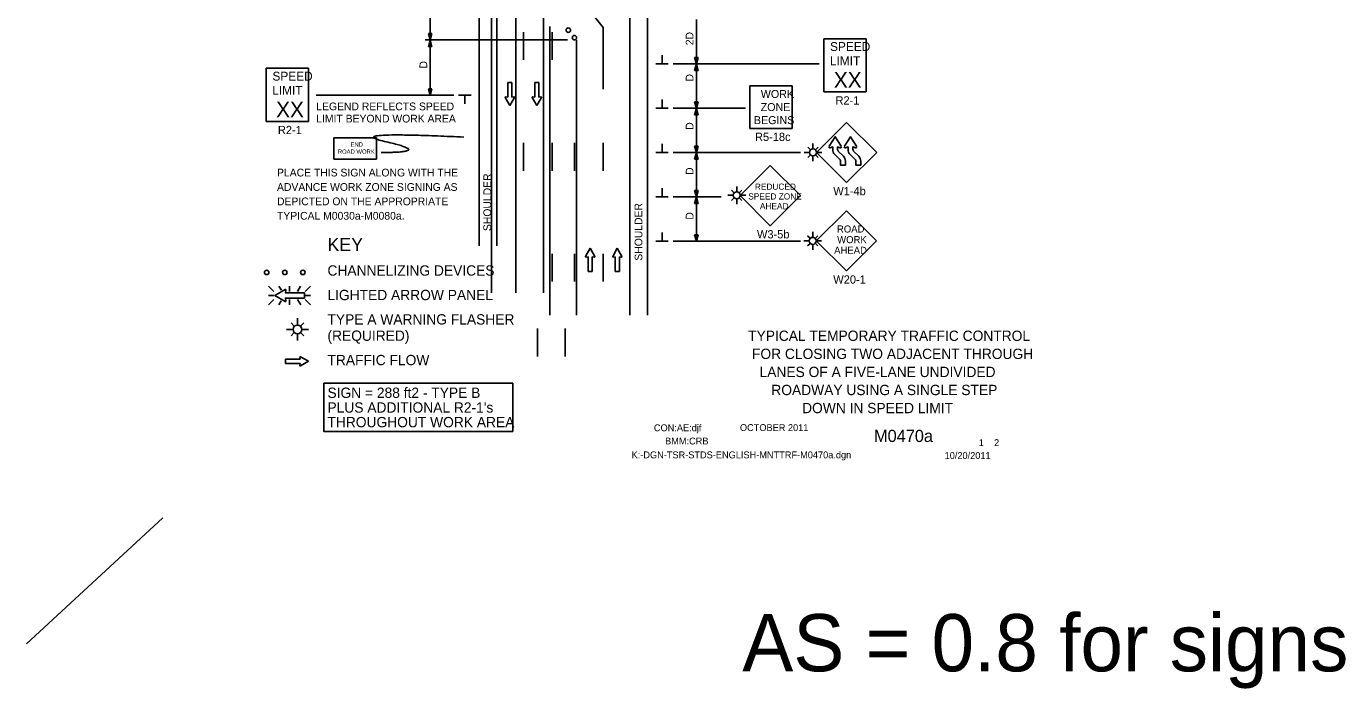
# Model space of a CAD drawing. Extents: x 16525 to 18475, y 5726 to 6926.
# Drawn here: x 16525 to 17715, y 5726 to 6323 of the extents above; entities that cross this region are included whole.
import ezdxf

# ---------------------------------------------------------------- set-up
doc = ezdxf.new("R2010")
doc.units = 0
for name, color, linetype in [('ALI_LEGAL_EX', 7, 'Continuous'), ('BORDER', 7, 'Continuous'), ('BORDER_SIGNAL_WO', 7, 'Continuous'), ('MT_SCRATCH_LEVEL_E', 7, 'Continuous'), ('PAVT_EDGE_EX', 7, 'Continuous'), ('TRAFFIC_SIGNS_PR', 7, 'Continuous'), ('TYPICAL_TEXT_DIMEN_EX', 7, 'Continuous'), ('TYPICAL_TEXT_DIMEN_PR', 7, 'Continuous')]:
    doc.layers.add(name, color=color, linetype=linetype)

msp = doc.modelspace()

# ---------------------------------------------------------------- linework, layer by layer
at = {"layer": 'ALI_LEGAL_EX'}
for points in [[(16973, 6318.2), (16973, 6293.2)], [(16999, 6318.2), (16999, 6293.2)], [(16973, 6218.2), (16973, 6193.2)], [(16999, 6218.2), (16999, 6193.2)], [(17019, 6218.2), (17019, 6193.2)], [(17045, 6218.2), (17045, 6193.2)], [(16999, 6118.2), (16999, 6093.2)], [(17019, 6118.2), (17019, 6093.2)], [(17045, 6118.2), (17045, 6093.2)]]:
    msp.add_lwpolyline(points, dxfattribs=at)
at = {"layer": 'MT_SCRATCH_LEVEL_E'}
for p, q in [((16962.7, 6272.8), (16958.9, 6272.8)), ((16958.9, 6272.8), (16958.9, 6259.6)), ((16962.7, 6272.8), (16958.9, 6272.8)), ((16958.9, 6272.8), (16958.9, 6259.6)), ((16962.7, 6259.6), (16962.7, 6272.8)), ((16962.7, 6259.6), (16962.7, 6272.8)), ((16986.9, 6272.8), (16983.2, 6272.8)), ((16983.2, 6272.8), (16983.2, 6259.6)), ((16986.9, 6272.8), (16983.2, 6272.8)), ((16983.2, 6272.8), (16983.2, 6259.6)), ((16986.9, 6259.6), (16986.9, 6272.8)), ((16986.9, 6259.6), (16986.9, 6272.8)), ((16956.7, 6259.2), (16960.8, 6252)), ((16956.7, 6259.2), (16960.8, 6252)), ((16958.9, 6259.6), (16957.1, 6259.9)), ((16958.9, 6259.6), (16957.1, 6259.9)), ((16960.8, 6252), (16964.9, 6259.2)), ((16960.8, 6252), (16964.9, 6259.2)), ((16964.4, 6259.9), (16962.7, 6259.6)), ((16964.4, 6259.9), (16962.7, 6259.6)), ((16980.9, 6259.2), (16985.1, 6252)), ((16980.9, 6259.2), (16985.1, 6252)), ((16983.2, 6259.6), (16981.4, 6259.9)), ((16983.2, 6259.6), (16981.4, 6259.9)), ((16985.1, 6252), (16989.2, 6259.2)), ((16985.1, 6252), (16989.2, 6259.2)), ((16988.7, 6259.9), (16986.9, 6259.6)), ((16988.7, 6259.9), (16986.9, 6259.6)), ((17033.2, 6123.2), (17029.1, 6115.9)), ((17033.2, 6123.2), (17029.1, 6115.9)), ((17037.4, 6115.9), (17033.2, 6123.2)), ((17037.4, 6115.9), (17033.2, 6123.2)), ((17057.7, 6123.2), (17053.6, 6115.9)), ((17057.7, 6123.2), (17053.6, 6115.9)), ((17061.9, 6115.9), (17057.7, 6123.2)), ((17061.9, 6115.9), (17057.7, 6123.2)), ((17029.6, 6115.3), (17031.4, 6115.6)), ((17029.6, 6115.3), (17031.4, 6115.6)), ((17031.4, 6115.6), (17031.4, 6102.3)), ((17031.4, 6115.6), (17031.4, 6102.3)), ((17035.1, 6102.3), (17035.1, 6115.6)), ((17035.1, 6115.6), (17036.9, 6115.3)), ((17035.1, 6102.3), (17035.1, 6115.6)), ((17035.1, 6115.6), (17036.9, 6115.3)), ((17054.1, 6115.3), (17055.9, 6115.6)), ((17054.1, 6115.3), (17055.9, 6115.6)), ((17055.9, 6115.6), (17055.9, 6102.3)), ((17055.9, 6115.6), (17055.9, 6102.3)), ((17059.6, 6102.3), (17059.6, 6115.6)), ((17059.6, 6115.6), (17061.4, 6115.3)), ((17059.6, 6102.3), (17059.6, 6115.6)), ((17059.6, 6115.6), (17061.4, 6115.3)), ((17031.4, 6102.3), (17035.1, 6102.3)), ((17031.4, 6102.3), (17035.1, 6102.3)), ((17055.9, 6102.3), (17059.6, 6102.3)), ((17055.9, 6102.3), (17059.6, 6102.3)), ((16771.7, 6023), (16758.4, 6023)), ((16758.4, 6023), (16758.4, 6019.3)), ((16771.7, 6023), (16758.4, 6023)), ((16758.4, 6023), (16758.4, 6019.3)), ((16771.3, 6024.8), (16771.7, 6023)), ((16771.3, 6024.8), (16771.7, 6023)), ((16779.3, 6021.2), (16772, 6025.3)), ((16779.3, 6021.2), (16772, 6025.3)), ((16772, 6017), (16779.3, 6021.2)), ((16772, 6017), (16779.3, 6021.2)), ((16758.4, 6019.3), (16771.7, 6019.3)), ((16758.4, 6019.3), (16771.7, 6019.3)), ((16771.7, 6019.3), (16771.3, 6017.5)), ((16771.7, 6019.3), (16771.3, 6017.5))]:
    msp.add_line(p, q, dxfattribs=at)
for centre, start, end in [((16957.1, 6259.4), 80.0362, 209.7731), ((16957.1, 6259.4), 80.0362, 209.7731), ((16964.5, 6259.4), 330.4248, 99.9638), ((16964.5, 6259.4), 330.4248, 99.9638), ((16981.3, 6259.4), 80.0362, 209.7731), ((16981.3, 6259.4), 80.0362, 209.7731), ((16988.8, 6259.4), 330.4248, 99.9638), ((16988.8, 6259.4), 330.4248, 99.9638), ((17029.5, 6115.7), 150.4248, 279.9638), ((17029.5, 6115.7), 150.4248, 279.9638), ((17037, 6115.7), 260.0362, 29.7731), ((17037, 6115.7), 260.0362, 29.7731), ((17054, 6115.7), 150.4248, 279.9638), ((17054, 6115.7), 150.4248, 279.9638), ((17061.5, 6115.7), 260.0362, 29.7731), ((17061.5, 6115.7), 260.0362, 29.7731), ((16771.8, 6024.9), 60.4248, 189.9638), ((16771.8, 6024.9), 60.4248, 189.9638), ((16771.8, 6017.4), 170.0362, 299.7731), ((16771.8, 6017.4), 170.0362, 299.7731)]:
    msp.add_arc(centre, 0.463, start, end, dxfattribs=at)
at = {"layer": 'PAVT_EDGE_EX'}
for p, q in [((16933, 6926.1), (16933, 6125.4)), ((16949, 6926.1), (16949, 6125.4)), ((17069, 6926.1), (17069, 6062.8)), ((17085, 6926.1), (17085, 6062.8)), ((16944.1, 6912.1), (16944.1, 6082.9)), ((16966.1, 6912.1), (16966.1, 6082.9)), ((16991.1, 6912.1), (16991.1, 6082.9)), ((16997, 6382), (17045, 6322.3)), ((16997, 6323.2), (16997, 6062.8)), ((17045, 6322.3), (17045, 6266.9)), ((17021, 6311.2), (17021, 6062.8))]:
    msp.add_line(p, q, dxfattribs=at)
for points in [[(16985.8, 6025.7), (16985.8, 6050.7)], [(16985.8, 6025.7), (16985.8, 6050.7)], [(17010.8, 6025.7), (17010.8, 6050.7)], [(17010.8, 6025.7), (17010.8, 6050.7)]]:
    msp.add_lwpolyline(points, dxfattribs=at)
at = {"layer": 'TRAFFIC_SIGNS_PR'}
for p, q in [((17243.9, 6312.3), (17282.3, 6312.3)), ((17243.9, 6264.3), (17243.9, 6312.3)), ((17282.3, 6264.3), (17282.3, 6312.3)), ((16740.9, 6285.6), (16779.3, 6285.6)), ((16740.9, 6237.6), (16740.9, 6285.6)), ((16779.3, 6237.6), (16779.3, 6285.6)), ((17177.1, 6231.4), (17177.1, 6269.8)), ((17177.1, 6269.8), (17215.5, 6269.8)), ((17215.5, 6231.4), (17215.5, 6269.8)), ((17243.9, 6264.3), (17282.3, 6264.3)), ((16740.9, 6237.6), (16779.3, 6237.6)), ((17237.4, 6209.7), (17264.5, 6236.8)), ((17264.5, 6236.8), (17291.7, 6209.7)), ((17177.1, 6231.4), (17215.5, 6231.4)), ((17231.7, 6212.2), (17229.6, 6214.3)), ((17234.2, 6213.2), (17234.2, 6217.7)), ((17236.7, 6212.2), (17238.8, 6214.3)), ((17261.6, 6206.2), (17256.9, 6210.9)), ((17256.9, 6210.9), (17261.6, 6206.2)), ((17275.4, 6206.2), (17270.7, 6210.9)), ((17270.7, 6210.9), (17275.4, 6206.2)), ((17231.1, 6209.7), (17226.2, 6209.7)), ((17231.7, 6207.2), (17229.6, 6205.1)), ((17234.2, 6201.7), (17234.2, 6206.1)), ((17236.7, 6207.2), (17238.8, 6205.1)), ((17237.4, 6209.7), (17242.3, 6209.7)), ((17264.5, 6182.5), (17237.4, 6209.7)), ((17258.5, 6203.2), (17253.8, 6207.9)), ((17258.5, 6203.2), (17253.8, 6207.9)), ((17259.1, 6198.1), (17259.1, 6201.8)), ((17263.5, 6198.1), (17263.5, 6201.8)), ((17291.7, 6209.7), (17264.5, 6182.5)), ((17272.3, 6203.2), (17267.6, 6207.9)), ((17272.3, 6203.2), (17267.6, 6207.9)), ((17272.9, 6198.1), (17272.9, 6201.8)), ((17277.3, 6198.1), (17277.3, 6201.8)), ((17195.7, 6197.8), (17168.6, 6170.7)), ((17222.9, 6170.7), (17195.7, 6197.8)), ((17263.5, 6198.1), (17259.1, 6198.1)), ((17277.3, 6198.1), (17272.9, 6198.1)), ((17162.9, 6173.5), (17160.8, 6175.6)), ((17165.4, 6174.5), (17165.4, 6179)), ((17168, 6173.5), (17170.1, 6175.6)), ((17162.3, 6171), (17157.5, 6171)), ((17162.9, 6168.4), (17160.8, 6166.3)), ((17165.4, 6163), (17165.4, 6167.4)), ((17168, 6168.4), (17170.1, 6166.3)), ((17168.6, 6171), (17173.5, 6171)), ((17168.6, 6170.7), (17195.7, 6143.5)), ((17195.7, 6143.5), (17222.9, 6170.7)), ((17264.3, 6157.1), (17237.1, 6129.9)), ((17291.5, 6129.9), (17264.3, 6157.1)), ((17230.8, 6129.9), (17226, 6129.9)), ((17231.5, 6132.4), (17229.3, 6134.5)), ((17234, 6133.5), (17234, 6138)), ((17236.5, 6132.4), (17238.6, 6134.5)), ((17237.1, 6129.9), (17242, 6129.9)), ((17237.1, 6129.9), (17264.3, 6102.7)), ((17264.3, 6102.7), (17291.5, 6129.9)), ((17231.5, 6127.4), (17229.3, 6125.3)), ((17234, 6121.9), (17234, 6126.3)), ((17236.5, 6127.4), (17238.6, 6125.3)), ((16743, 6089.1), (16747.9, 6084.2)), ((16747.9, 6080.6), (16743, 6080.6)), ((16754.7, 6085.3), (16752.5, 6089.1)), ((16762, 6084.2), (16762, 6089.1)), ((16769.3, 6084.2), (16772.1, 6089.1)), ((16776.2, 6084.2), (16781.1, 6089.1)), ((16776.2, 6080.6), (16781.1, 6080.6)), ((16743, 6072.1), (16747.9, 6077)), ((16752.5, 6072.1), (16754.6, 6075.8)), ((16762, 6077), (16762, 6072.1)), ((16772.2, 6072.1), (16769.3, 6077)), ((16776.2, 6077), (16781.1, 6072.1)), ((16769.2, 6054.4), (16769.2, 6060.1)), ((16769.2, 6054.4), (16769.2, 6060.1)), ((16765.3, 6050), (16759.3, 6050)), ((16765.3, 6050), (16759.3, 6050)), ((16766.1, 6053.1), (16763.5, 6055.8)), ((16766.1, 6053.1), (16763.5, 6055.8)), ((16766.1, 6046.9), (16763.5, 6044.2)), ((16766.1, 6046.9), (16763.5, 6044.2)), ((16769.2, 6040.1), (16769.2, 6045.6)), ((16769.2, 6040.1), (16769.2, 6045.6)), ((16772.4, 6053.1), (16775, 6055.8)), ((16772.4, 6053.1), (16775, 6055.8)), ((16772.4, 6046.9), (16775, 6044.2)), ((16772.4, 6046.9), (16775, 6044.2)), ((16773.2, 6050), (16779.3, 6050)), ((16773.2, 6050), (16779.3, 6050))]:
    msp.add_line(p, q, dxfattribs=at)
msp.add_lwpolyline([(16802.1, 6203.7), (16840.5, 6203.7), (16840.5, 6222.9), (16802.1, 6222.9)], close=True, dxfattribs=at)
for points in [[(17248.7, 6215.2), (17254.2, 6223.8), (17259.6, 6215.2)], [(17248.7, 6215.2), (17254.2, 6223.8), (17259.6, 6215.2)], [(17262.5, 6215.2), (17268, 6223.8), (17273.4, 6215.2)], [(17262.5, 6215.2), (17268, 6223.8), (17273.4, 6215.2)], [(17252, 6212.2), (17252, 6214.6), (17249.6, 6213.9)], [(17252, 6212.2), (17252, 6214.6), (17249.6, 6213.9)], [(17258.7, 6213.9), (17256.3, 6214.6), (17256.3, 6212.3)], [(17258.7, 6213.9), (17257.8, 6214.1), (17256.3, 6214.6), (17256.3, 6212.3)], [(17265.8, 6212.2), (17265.8, 6214.6), (17263.4, 6213.9)], [(17265.8, 6212.2), (17265.8, 6214.6), (17263.4, 6213.9)], [(17272.5, 6213.9), (17270.1, 6214.6), (17270.1, 6212.3)], [(17272.5, 6213.9), (17271.6, 6214.1), (17270.1, 6214.6), (17270.1, 6212.3)], [(17263.5, 6201.8), (17263.5, 6198.1), (17259.1, 6198.1), (17259.1, 6201.8)], [(17277.3, 6201.8), (17277.3, 6198.1), (17272.9, 6198.1), (17272.9, 6201.8)], [(16758, 6085.9), (16748.7, 6080.6), (16758, 6075.3)], [(16758.8, 6075.9), (16758.4, 6078.2), (16775.5, 6078.2), (16775.5, 6083), (16758.4, 6083), (16758.8, 6085.3)]]:
    msp.add_lwpolyline(points, dxfattribs=at)
for centre, radius in [((17013.5, 6320), 2), ((17019, 6313.2), 2), ((17234.2, 6209.7), 3.15), ((17165.4, 6171), 3.15), ((17234, 6129.9), 3.15), ((16741.5, 6101.4), 2), ((16757.8, 6101.4), 2), ((16774.1, 6101.4), 2), ((16769.2, 6050), 3.94), ((16769.2, 6050), 3.94)]:
    msp.add_circle(centre, radius, dxfattribs=at)
for centre, radius, start, end in [((17249.4, 6214.7), 0.866, 147.7292, 285.3172), ((17249.4, 6214.7), 0.866, 147.7196, 285.3201), ((17239.6, 6221), 10.8, 327.5335, 327.5431), ((17252.5, 6203.5), 10.8, 105.3192, 105.32), ((17258.2, 6212.3), 6.17, 180.6181, 225.7875), ((17258.2, 6212.3), 6.17, 180.6245, 225.2313), ((17258.2, 6212.3), 1.85, 180, 225.7875), ((17258.2, 6212.3), 1.85, 179.8762, 225.7877), ((17258.9, 6214.7), 0.864, 254.6014, 32.4796), ((17258.9, 6214.7), 0.866, 254.6148, 32.4712), ((17263.2, 6214.7), 0.866, 147.7292, 285.3172), ((17263.2, 6214.7), 0.866, 147.7196, 285.3201), ((17253.4, 6221), 10.8, 327.5335, 327.5431), ((17266.3, 6203.5), 10.8, 105.3192, 105.32), ((17272, 6212.3), 6.17, 180.6181, 225.7875), ((17272, 6212.3), 6.17, 180.6245, 225.2313), ((17272, 6212.3), 1.85, 180, 225.7875), ((17272, 6212.3), 1.85, 179.8762, 225.7877), ((17272.7, 6214.7), 0.864, 254.6014, 32.4796), ((17272.7, 6214.7), 0.866, 254.6148, 32.4712), ((17257.3, 6201.8), 1.85, 0, 47.628), ((17257.3, 6201.8), 1.85, 0, 45.7875), ((17257.3, 6201.8), 6.17, 0, 45.7875), ((17257.3, 6201.8), 6.17, 0, 45.7875), ((17257.3, 6201.8), 6.17, 0, 45.7883), ((17271.1, 6201.8), 1.85, 0, 47.628), ((17271.1, 6201.8), 1.85, 0, 45.7875), ((17271.1, 6201.8), 6.17, 0, 45.7875), ((17271.1, 6201.8), 6.17, 0, 45.7875), ((17271.1, 6201.8), 6.17, 0, 45.7883), ((16758.3, 6085.4), 0.598, 350.7308, 118.8916), ((16758.3, 6075.8), 0.597, 241.4833, 9.9593)]:
    msp.add_arc(centre, radius, start, end, dxfattribs=at)
msp.add_open_spline([(16844.7, 6209.6), (16891.9, 6209.6), (16806.9, 6228.9), (16919.2, 6223.5)], degree=2, dxfattribs=at)
at = {"layer": 'TYPICAL_TEXT_DIMEN_EX'}
msp.add_lwpolyline([(16793, 6001.4), (16963.4, 6001.4), (16963.4, 5958), (16793, 5958)], close=True, dxfattribs=at)
at = {"layer": 'TYPICAL_TEXT_DIMEN_PR'}
for p, q in [((16888.9, 6311.2), (16888.9, 6369.8)), ((17129, 6329.5), (17129, 6289.5)), ((16884.3, 6311.2), (17012.7, 6311.2)), ((16888.9, 6311.2), (16887.3, 6317)), ((16887.3, 6317), (16888.9, 6317)), ((16887.3, 6305.3), (16888.9, 6311.2)), ((16888.9, 6317), (16890.5, 6317)), ((16890.5, 6317), (16888.9, 6311.2)), ((16888.9, 6261.2), (16888.9, 6311.2)), ((16888.9, 6311.2), (16890.5, 6305.3)), ((16888.9, 6305.3), (16887.3, 6305.3)), ((16890.5, 6305.3), (16888.9, 6305.3)), ((17098.1, 6289.5), (17098.1, 6297.3)), ((17129, 6289.5), (17127.4, 6295.4)), ((17127.4, 6295.4), (17129, 6295.4)), ((17129, 6295.4), (17130.6, 6295.4)), ((17130.6, 6295.4), (17129, 6289.5)), ((17103.7, 6289.5), (17092.5, 6289.5)), ((17239.7, 6289.5), (17108, 6289.5)), ((17127.4, 6283.7), (17129, 6289.5)), ((17129, 6283.7), (17127.4, 6283.7)), ((17129, 6289.5), (17130.6, 6283.7)), ((17129, 6289.5), (17129, 6249.5)), ((17130.6, 6283.7), (17129, 6283.7)), ((16910.3, 6261.2), (16786, 6261.2)), ((16888.9, 6261.2), (16887.3, 6267)), ((16887.3, 6267), (16888.9, 6267)), ((16888.9, 6267), (16890.5, 6267)), ((16890.5, 6267), (16888.9, 6261.2)), ((16914.5, 6261.2), (16925.8, 6261.2)), ((16920.1, 6261.2), (16920.1, 6253.4)), ((17103.7, 6249.5), (17092.5, 6249.5)), ((17098.1, 6249.5), (17098.1, 6257.3)), ((17108, 6249.5), (17173.4, 6249.5)), ((17129, 6249.5), (17127.4, 6255.4)), ((17127.4, 6255.4), (17129, 6255.4)), ((17127.4, 6243.7), (17129, 6249.5)), ((17129, 6255.4), (17130.6, 6255.4)), ((17130.6, 6255.4), (17129, 6249.5)), ((17129, 6249.5), (17130.6, 6243.7)), ((17129, 6249.5), (17129, 6209.5)), ((17129, 6243.7), (17127.4, 6243.7)), ((17130.6, 6243.7), (17129, 6243.7)), ((17098.1, 6209.5), (17098.1, 6217.3)), ((17129, 6209.5), (17127.4, 6215.4)), ((17127.4, 6215.4), (17129, 6215.4)), ((17129, 6215.4), (17130.6, 6215.4)), ((17130.6, 6215.4), (17129, 6209.5)), ((17103.7, 6209.5), (17092.5, 6209.5)), ((17108, 6209.5), (17223, 6209.5)), ((17127.4, 6203.7), (17129, 6209.5)), ((17129, 6203.7), (17127.4, 6203.7)), ((17129, 6209.5), (17130.6, 6203.7)), ((17129, 6209.5), (17129, 6169.5)), ((17130.6, 6203.7), (17129, 6203.7)), ((17098.1, 6169.5), (17098.1, 6177.3)), ((17129, 6169.5), (17127.4, 6175.4)), ((17127.4, 6175.4), (17129, 6175.4)), ((17129, 6175.4), (17130.6, 6175.4)), ((17130.6, 6175.4), (17129, 6169.5)), ((17103.7, 6169.5), (17092.5, 6169.5)), ((17151.5, 6169.5), (17108, 6169.5)), ((17127.4, 6163.7), (17129, 6169.5)), ((17129, 6163.7), (17127.4, 6163.7)), ((17129, 6169.5), (17130.6, 6163.7)), ((17129, 6169.5), (17129, 6129.5)), ((17130.6, 6163.7), (17129, 6163.7)), ((17103.7, 6129.5), (17092.5, 6129.5)), ((17098.1, 6129.5), (17098.1, 6137.3)), ((17108, 6129.5), (17223, 6129.5)), ((17129, 6129.5), (17127.4, 6135.4)), ((17127.4, 6135.4), (17129, 6135.4)), ((17129, 6135.4), (17130.6, 6135.4)), ((17130.6, 6135.4), (17129, 6129.5)), ((16647.8, 5880), (16524.8, 5766.2))]:
    msp.add_line(p, q, dxfattribs=at)

# ---------------------------------------------------------------- texts
at = {"layer": 'BORDER'}
for s, p in [('TYPICAL TEMPORARY TRAFFIC CONTROL', (17175.7, 6039.6)), ('FOR CLOSING TWO ADJACENT THROUGH', (17179.2, 6023.3)), ('LANES OF A FIVE-LANE UNDIVIDED', (17186, 6007)), ('ROADWAY USING A SINGLE STEP', (17196.6, 5990.7)), ('DOWN IN SPEED LIMIT', (17224.4, 5974.4))]:
    msp.add_text(s, height=9.3, dxfattribs=at).set_placement(p)
at = {"layer": 'BORDER_SIGNAL_WO'}
for s, height, p in [('CON:AE:djf', 6.2, (17090.7, 5958.1)), ('    OCTOBER 2011    ', 6.2, (17159.1, 5958.3)), ('BMM:CRB   ', 6.2, (17100.8, 5946.2)), ('    M0470a   ', 11, (17272.9, 5948.4)), (' 1    2 ', 6.2, (17381.4, 5944.7)), ('K:-DGN-TSR-STDS-ENGLISH-MNTTRF-M0470a.dgn        ', 6.2, (17070.6, 5933.7)), ('10/20/2011    ', 6.2, (17352.9, 5933.1)), ('AS = 0.8 for signs', 51.61, (17170.4, 5741.5))]:
    msp.add_text(s, height=height, dxfattribs=at).set_placement(p)
at = {"layer": 'TRAFFIC_SIGNS_PR'}
for s, height, p in [('SPEED', 8, (17249.6, 6301.2)), ('LIMIT', 8, (17249.5, 6288.4)), ('SPEED', 8, (16746.7, 6274.5)), ('XX', 14.03, (17253, 6268.1)), ('LIMIT', 8, (16746.5, 6261.7)), ('WORK', 7.22, (17187.1, 6258.8)), ('R2-1', 7.44, (17254.5, 6252.9)), ('XX', 14.03, (16750, 6241.4)), ('ZONE', 7.22, (17187, 6247)), ('BEGINS', 7.22, (17180.9, 6235.2)), ('R2-1', 7.44, (16751.6, 6226.2)), ('R5-18c', 7.44, (17181.9, 6220)), ('ROAD WORK', 3.83, (16805.7, 6208.5)), ('END', 3.83, (16817.1, 6214.9)), ('PLACE THIS SIGN ALONG WITH THE', 7, (16750.8, 6188)), ('ADVANCE WORK ZONE SIGNING AS', 7, (16750.8, 6175)), ('REDUCED', 5.6, (17181.8, 6176)), ('W1-4b', 7.44, (17252.5, 6171.1)), ('DEPICTED ON THE APPROPRIATE', 7, (16750.8, 6162)), ('SPEED ZONE', 5.6, (17175.8, 6167.2)), ('AHEAD', 5.6, (17186.3, 6158.4)), ('TYPICAL M0030a-M0080a.', 7, (16750.8, 6149)), ('W3-5b', 7.44, (17183.7, 6132.1)), ('ROAD', 6.41, (17255.8, 6137.4)), ('WORK', 6.41, (17256, 6127.8)), ('AHEAD', 6.41, (17253.3, 6118.2)), ('W20-1', 7.45, (17252.5, 6091.3))]:
    msp.add_text(s, height=height, dxfattribs=at).set_placement(p)
at = {"layer": 'TYPICAL_TEXT_DIMEN_EX'}
for s, height, p in [('KEY', 12, (16796.3, 6120.6)), ('CHANNELIZING DEVICES', 9.3, (16796.3, 6098.5)), ('LIGHTED ARROW PANEL', 9.3, (16796.3, 6076.4)), ('TYPE A WARNING FLASHER', 9.3, (16796.3, 6054.4)), ('(REQUIRED)', 9.3, (16796.3, 6039.7)), ('TRAFFIC FLOW', 9.3, (16796.3, 6017.7)), ('SIGN = 288 ft2 - TYPE B', 9.3, (16796.3, 5988.2)), ("PLUS ADDITIONAL R2-1's", 9.3, (16796.3, 5974.9)), ('THROUGHOUT WORK AREA', 9.3, (16796.3, 5961.7))]:
    msp.add_text(s, height=height, dxfattribs=at).set_placement(p)
at = {"layer": 'TYPICAL_TEXT_DIMEN_PR'}
for s, p in [('2D', (17126.4, 6306.4)), ('D', (16886.3, 6285.4)), ('D', (17126.4, 6273.7)), ('D', (17126.4, 6230.1)), ('SHOULDER', (16943.9, 6138.7)), ('D', (17126.4, 6189.4)), ('SHOULDER', (17080.3, 6112)), ('D', (17126.4, 6149))]:
    msp.add_text(s, height=7, rotation=90, dxfattribs=at).set_placement(p)
for s, p in [('LEGEND REFLECTS SPEED', (16786.2, 6247.7)), ('LIMIT BEYOND WORK AREA', (16786.2, 6236.7))]:
    msp.add_text(s, height=7, dxfattribs=at).set_placement(p)

doc.saveas('drawing.dxf')
